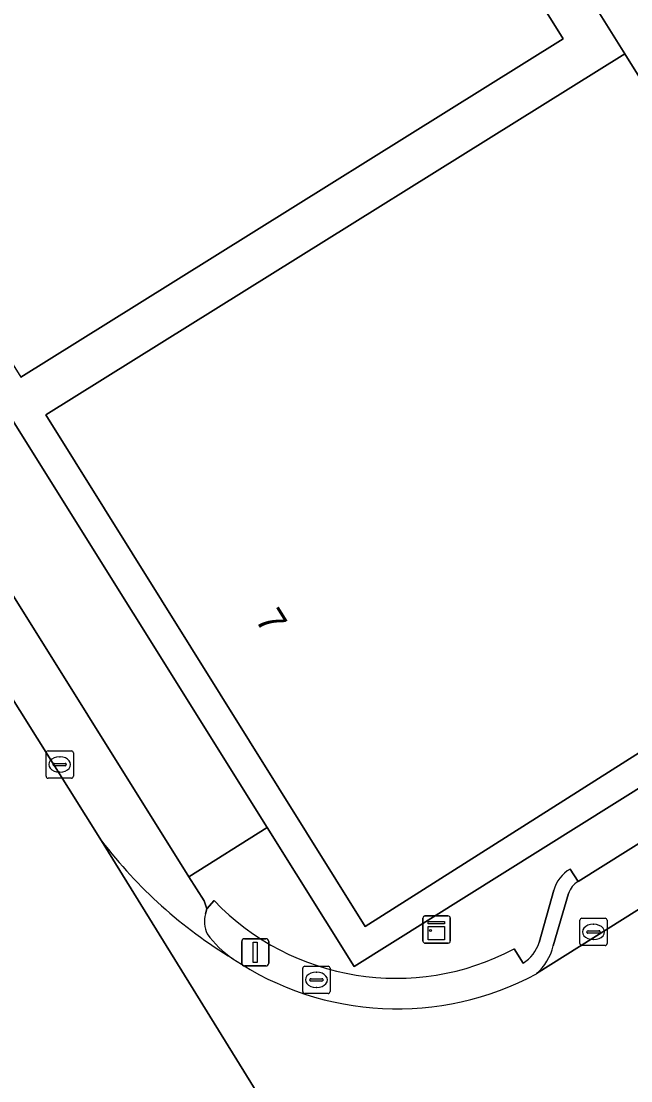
# Model space of a CAD drawing. Extents: x 158455 to 159797, y 387218 to 388672.
# Drawn here: x 158705.05 to 158727.38, y 387757.54 to 387796.36 of the extents above; entities that cross this region are included whole.
import ezdxf

# ---------------------------------------------------------------- set-up
doc = ezdxf.new("R2010")
doc.units = 0
for name, color, linetype in [('IMGEO_Brandkraan', 7, 'Continuous'), ('IMGEO_Erf', 7, 'Continuous'), ('IMGEO_Kast', 7, 'Continuous'), ('IMGEO_Kolk', 7, 'Continuous'), ('IMGEO_Lichtmast', 7, 'Continuous'), ('IMGEO_Pand', 7, 'Continuous'), ('IMGEO_Pand_nummerreeks', 7, 'Continuous'), ('IMGEO_Parkeervlak_open', 7, 'Continuous'), ('IMGEO_Rijbaan_lokaal_gesloten', 7, 'Continuous'), ('IMGEO_Voetpad_open', 7, 'Continuous')]:
    doc.layers.add(name, color=color, linetype=linetype)

msp = doc.modelspace()

# ---------------------------------------------------------------- linework, layer by layer
at = {"layer": 'IMGEO_Brandkraan'}
for p, q in [((158715.44, 387761.734), (158716.292, 387761.734)), ((158715.365, 387760.808), (158715.365, 387761.66)), ((158715.853, 387761.514), (158715.878, 387761.514)), ((158716.366, 387761.66), (158716.366, 387760.808)), ((158715.624, 387761.228), (158715.624, 387761.24)), ((158716.062, 387761.191), (158715.664, 387761.191)), ((158715.667, 387761.277), (158716.065, 387761.277)), ((158715.876, 387760.954), (158715.851, 387760.954)), ((158716.108, 387761.24), (158716.108, 387761.228)), ((158716.292, 387760.734), (158715.44, 387760.734))]:
    msp.add_line(p, q, dxfattribs=at)
for points in [[(158715.44, 387761.734), (158716.292, 387761.734)], [(158715.365, 387760.808), (158715.365, 387761.66)], [(158716.366, 387761.66), (158716.366, 387760.808)], [(158716.292, 387760.734), (158715.44, 387760.734)]]:
    msp.add_lwpolyline(points, dxfattribs=at)
for centre, radius, start, end in [((158715.442, 387761.658), 0.0765, 91.552, 178.448), ((158715.442, 387761.658), 0.0765, 91.552, 178.448), ((158716.29, 387761.658), 0.0765, 1.552, 88.448), ((158716.29, 387761.658), 0.0765, 1.552, 88.448), ((158715.664, 387761.237), 0.0403, 85.8775, 175.7526), ((158715.661, 387761.227), 0.0366, 178.938, 274.7102), ((158716.065, 387761.234), 0.043, 264.8664, 352.4533), ((158716.069, 387761.239), 0.0386, 1.7309, 96.639), ((158715.442, 387760.81), 0.0765, 181.552, 268.448), ((158715.442, 387760.81), 0.0765, 181.552, 268.448), ((158716.29, 387760.81), 0.0765, 271.552, 358.448), ((158716.29, 387760.81), 0.0765, 271.552, 358.448)]:
    msp.add_arc(centre, radius, start, end, dxfattribs=at)
for centre, major_axis, ratio, start_param, end_param in [((158715.852, 387761.234), (-0.387, 0.002), 0.722429, 4.712389, 7.853982), ((158715.877, 387761.234), (-0.39, 0.002), 0.717154, 1.570796, 4.712389)]:
    msp.add_ellipse(centre, major_axis=major_axis, ratio=ratio, start_param=start_param, end_param=end_param, dxfattribs=at)
at = {"layer": 'IMGEO_Erf'}
for points in [[(158707.009, 387857.672), (158697.055, 387851.465), (158693.417, 387849.212), (158672.211, 387835.913), (158671.304, 387835.407), (158671.246, 387835.269), (158671.606, 387834.665), (158691.111, 387803.48), (158696.218, 387795.316), (158699.252, 387790.473), (158714.054, 387766.818), (158717.252, 387761.719), (158733.714, 387772.034), (158739.37, 387775.529), (158743.923, 387778.371), (158747.2, 387780.372), (158755.504, 387785.603)], [(158721.98, 387832.89), (158732.099, 387816.668), (158727.857, 387814.022), (158718.906, 387808.438), (158719.649, 387807.206), (158730.844, 387814.188), (158735.086, 387816.834), (158751.068, 387791.209), (158735.631, 387781.581), (158738.754, 387776.575), (158717.649, 387763.184), (158705.955, 387781.931), (158710.198, 387784.578), (158727.162, 387795.16), (158720.877, 387805.237), (158719.499, 387804.377), (158724.907, 387795.706), (158709.281, 387785.958), (158705.038, 387783.311)]]:
    msp.add_lwpolyline(points, dxfattribs=at)
at = {"layer": 'IMGEO_Kast'}
for p, q in [((158719.768, 387762.652), (158719.768, 387763.493)), ((158719.768, 387763.493), (158719.768, 387762.652)), ((158719.843, 387763.577), (158720.684, 387763.577)), ((158720.684, 387763.577), (158719.843, 387763.577)), ((158720.768, 387763.502), (158720.768, 387762.661)), ((158720.768, 387762.661), (158720.768, 387763.502)), ((158720.693, 387762.577), (158719.852, 387762.577)), ((158719.852, 387762.577), (158720.693, 387762.577))]:
    msp.add_line(p, q, dxfattribs=at)
for points in [[(158719.963, 387763.367), (158720.563, 387763.367), (158720.563, 387763.282), (158719.963, 387763.282), (158719.963, 387763.367)], [(158719.963, 387763.192), (158720.563, 387763.192), (158720.563, 387762.703), (158719.963, 387762.703), (158719.963, 387763.192)]]:
    msp.add_lwpolyline(points, dxfattribs=at)
msp.add_circle((158720.047, 387763.041), 0.0377, dxfattribs=at)
for centre, start, end in [((158719.846, 387763.499), 92.4484, 184.2845), ((158719.846, 387763.499), 92.4484, 184.2845), ((158720.69, 387763.499), 2.4484, 94.2845), ((158720.69, 387763.499), 2.4484, 94.2845), ((158719.846, 387762.655), 182.4484, 274.2845), ((158719.846, 387762.655), 182.4484, 274.2845), ((158720.69, 387762.655), 272.4484, 4.2845), ((158720.69, 387762.655), 272.4484, 4.2845)]:
    msp.add_arc(centre, 0.0779, start, end, dxfattribs=at)
at = {"layer": 'IMGEO_Kolk'}
for p, q in [((158705.958, 387768.697), (158705.958, 387769.549)), ((158706.033, 387769.623), (158706.885, 387769.623)), ((158706.959, 387769.549), (158706.959, 387768.697)), ((158706.217, 387769.117), (158706.217, 387769.129)), ((158706.655, 387769.08), (158706.257, 387769.08)), ((158706.26, 387769.166), (158706.658, 387769.166)), ((158706.446, 387769.403), (158706.471, 387769.403)), ((158706.701, 387769.129), (158706.701, 387769.117)), ((158706.469, 387768.843), (158706.444, 387768.843)), ((158706.885, 387768.623), (158706.033, 387768.623)), ((158725.516, 387762.564), (158725.516, 387763.416)), ((158725.591, 387763.49), (158726.443, 387763.49)), ((158726.004, 387763.27), (158726.029, 387763.27)), ((158726.517, 387763.416), (158726.517, 387762.564)), ((158725.775, 387762.984), (158725.775, 387762.996)), ((158726.213, 387762.947), (158725.815, 387762.947)), ((158725.818, 387763.033), (158726.216, 387763.033)), ((158726.259, 387762.996), (158726.259, 387762.984)), ((158726.443, 387762.49), (158725.591, 387762.49)), ((158726.027, 387762.71), (158726.002, 387762.71))]:
    msp.add_line(p, q, dxfattribs=at)
for points in [[(158705.958, 387768.697), (158705.958, 387769.549)], [(158706.033, 387769.623), (158706.885, 387769.623)], [(158706.959, 387769.549), (158706.959, 387768.697)], [(158706.885, 387768.623), (158706.033, 387768.623)], [(158725.516, 387762.564), (158725.516, 387763.416)], [(158725.591, 387763.49), (158726.443, 387763.49)], [(158726.517, 387763.416), (158726.517, 387762.564)], [(158726.443, 387762.49), (158725.591, 387762.49)]]:
    msp.add_lwpolyline(points, dxfattribs=at)
for centre, radius, start, end in [((158706.035, 387769.547), 0.0765, 91.552, 178.448), ((158706.035, 387769.547), 0.0765, 91.552, 178.448), ((158706.883, 387769.547), 0.0765, 1.552, 88.448), ((158706.883, 387769.547), 0.0765, 1.552, 88.448), ((158706.257, 387769.126), 0.0403, 85.8775, 175.7526), ((158706.254, 387769.116), 0.0366, 178.938, 274.7102), ((158706.658, 387769.123), 0.043, 264.8664, 352.4533), ((158706.662, 387769.128), 0.0386, 1.7309, 96.639), ((158706.035, 387768.699), 0.0765, 181.552, 268.448), ((158706.035, 387768.699), 0.0765, 181.552, 268.448), ((158706.883, 387768.699), 0.0765, 271.552, 358.448), ((158706.883, 387768.699), 0.0765, 271.552, 358.448), ((158725.593, 387763.414), 0.0765, 91.552, 178.448), ((158725.593, 387763.414), 0.0765, 91.552, 178.448), ((158726.441, 387763.414), 0.0765, 1.552, 88.448), ((158726.441, 387763.414), 0.0765, 1.552, 88.448), ((158725.815, 387762.993), 0.0403, 85.8775, 175.7526), ((158725.812, 387762.983), 0.0366, 178.938, 274.7102), ((158726.216, 387762.99), 0.043, 264.8664, 352.4533), ((158726.22, 387762.995), 0.0386, 1.7309, 96.639), ((158725.593, 387762.566), 0.0765, 181.552, 268.448), ((158725.593, 387762.566), 0.0765, 181.552, 268.448), ((158726.441, 387762.566), 0.0765, 271.552, 358.448), ((158726.441, 387762.566), 0.0765, 271.552, 358.448)]:
    msp.add_arc(centre, radius, start, end, dxfattribs=at)
for centre, major_axis, ratio, start_param, end_param in [((158706.445, 387769.123), (-0.387, 0.002), 0.722429, 4.712389, 7.853982), ((158706.47, 387769.123), (-0.39, 0.002), 0.717154, 1.570796, 4.712389), ((158726.003, 387762.99), (-0.387, 0.002), 0.722429, 4.712389, 7.853982), ((158726.028, 387762.99), (-0.39, 0.002), 0.717154, 1.570796, 4.712389)]:
    msp.add_ellipse(centre, major_axis=major_axis, ratio=ratio, start_param=start_param, end_param=end_param, dxfattribs=at)
at = {"layer": 'IMGEO_Lichtmast'}
for p, q in [((158713.126, 387761.843), (158713.126, 387762.643)), ((158713.126, 387762.643), (158713.126, 387761.843)), ((158713.226, 387762.743), (158714.016, 387762.743)), ((158714.016, 387762.743), (158713.226, 387762.743)), ((158714.116, 387762.643), (158714.116, 387761.843)), ((158714.116, 387761.843), (158714.116, 387762.643)), ((158714.016, 387761.743), (158713.226, 387761.743)), ((158713.226, 387761.743), (158714.016, 387761.743))]:
    msp.add_line(p, q, dxfattribs=at)
msp.add_lwpolyline([(158713.546, 387762.618), (158713.696, 387762.618), (158713.696, 387761.868), (158713.546, 387761.868), (158713.546, 387762.618)], dxfattribs=at)
for centre, start, end in [((158713.226, 387762.643), 90, 180), ((158713.226, 387762.643), 90, 180), ((158714.016, 387762.643), 0, 90), ((158714.016, 387762.643), 360, 90), ((158713.226, 387761.843), 180, 270), ((158713.226, 387761.843), 180, 270), ((158714.016, 387761.843), 270, 0), ((158714.016, 387761.843), 270, 0)]:
    msp.add_arc(centre, 0.1, start, end, dxfattribs=at)
at = {"layer": 'IMGEO_Pand'}
for points in [[(158720.877, 387805.237), (158727.162, 387795.16), (158735.631, 387781.581), (158751.068, 387791.209), (158735.086, 387816.834), (158730.844, 387814.188), (158719.649, 387807.206)], [(158718.906, 387808.438), (158715.842, 387813.35), (158714.709, 387815.167), (158709.613, 387811.988), (158711.297, 387809.289), (158708.207, 387807.361), (158709.969, 387804.536), (158701.131, 387799.023), (158696.888, 387796.376), (158705.038, 387783.311), (158709.281, 387785.958), (158724.907, 387795.706), (158719.499, 387804.377), (158720.877, 387805.237), (158719.649, 387807.206)], [(158727.162, 387795.16), (158710.198, 387784.578), (158705.955, 387781.931), (158717.649, 387763.184), (158738.754, 387776.575), (158735.631, 387781.581)]]:
    msp.add_lwpolyline(points, close=True, dxfattribs=at)
at = {"layer": 'IMGEO_Parkeervlak_open'}
for points in [[(158672.195, 387823.443), (158707.993, 387766.325)], [(158711.804, 387763.653), (158711.846, 387763.835), (158711.756, 387764.131), (158711.195, 387765.014), (158696.373, 387788.699), (158693.355, 387793.532), (158688.249, 387801.704), (158675.809, 387821.598), (158675.707, 387821.76)], [(158723.929, 387761.461), (158754.714, 387780.793)], [(158753.203, 387780.588), (158751.579, 387780.973), (158751.114, 387780.903), (158748.076, 387778.986), (158744.813, 387776.947), (158740.279, 387774.095), (158734.618, 387770.583), (158725.456, 387764.842)], [(158725.104, 387764.395), (158724.544, 387762.478)]]:
    msp.add_lwpolyline(points, dxfattribs=at)
for centre, radius, start, end in [((158721.752, 387776.82), 17.304, 217.3349, 238.8516), ((158725.851, 387764.169), 0.78, 120.3922, 163.1689), ((158712.8, 387763.36), 1.039, 163.6403, 205.0973), ((158714.993, 387765.218), 3.886, 216.2628, 235.6562), ((158722.56, 387762.983), 2.047, 311.9624, 345.7132)]:
    msp.add_arc(centre, radius, start, end, dxfattribs=at)
at = {"layer": 'IMGEO_Rijbaan_lokaal_gesloten'}
for points in [[(158701.625, 387760.45), (158716.254, 387737.492), (158717.377, 387735.852), (158725.058, 387738.734), (158724.913, 387738.934), (158707.993, 387766.325), (158672.195, 387823.443), (158671.961, 387823.816)], [(158756.204, 387781.781), (158754.714, 387780.793), (158723.929, 387761.461)], [(158707.993, 387766.325), (158724.913, 387738.934), (158725.058, 387738.734)]]:
    msp.add_lwpolyline(points, dxfattribs=at)
for centre, radius, start, end in [((158721.752, 387776.82), 17.304, 217.3349, 238.8516), ((158718.819, 387770.936), 10.766, 236.0133, 298.3379)]:
    msp.add_arc(centre, radius, start, end, dxfattribs=at)
at = {"layer": 'IMGEO_Voetpad_open'}
msp.add_lwpolyline([(158711.195, 387765.014), (158714.054, 387766.818), (158699.252, 387790.473), (158696.373, 387788.699)], close=True, dxfattribs=at)
for points in [[(158725.165, 387765.292), (158725.456, 387764.842), (158734.618, 387770.583), (158733.714, 387772.034), (158717.252, 387761.719), (158714.054, 387766.818), (158711.195, 387765.014), (158711.756, 387764.131), (158711.846, 387763.835), (158712.113, 387764.136)], [(158725.456, 387764.842), (158725.165, 387765.292)], [(158724.559, 387764.515), (158724.031, 387762.605)], [(158724.031, 387762.605), (158724.559, 387764.515)], [(158712.113, 387764.136), (158711.846, 387763.835), (158711.804, 387763.653)], [(158724.544, 387762.478), (158725.104, 387764.395)], [(158723.44, 387761.843), (158723.11, 387762.368)], [(158723.11, 387762.368), (158723.44, 387761.843)]]:
    msp.add_lwpolyline(points, dxfattribs=at)
for centre, radius, start, end in [((158725.801, 387764.171), 1.288, 119.5659, 164.5312), ((158725.801, 387764.171), 1.288, 119.5659, 164.5312), ((158725.851, 387764.169), 0.78, 120.3922, 163.1689), ((158718.782, 387770.533), 9.241, 223.8056, 297.9277), ((158718.782, 387770.533), 9.241, 223.8056, 297.9277), ((158712.8, 387763.36), 1.039, 163.6403, 205.0973), ((158714.993, 387765.218), 3.886, 216.2628, 235.6562), ((158722.662, 387763.057), 1.442, 302.6656, 341.7407), ((158722.662, 387763.057), 1.442, 302.6656, 341.7407), ((158722.56, 387762.983), 2.047, 311.9624, 345.7132), ((158718.819, 387770.936), 10.766, 236.0133, 298.3379)]:
    msp.add_arc(centre, radius, start, end, dxfattribs=at)

# ---------------------------------------------------------------- texts
at = {"layer": 'IMGEO_Pand_nummerreeks'}
msp.add_text('7', height=1, rotation=301.9551, dxfattribs=at).set_placement((158713.599, 387774.439))

doc.saveas('drawing.dxf')
